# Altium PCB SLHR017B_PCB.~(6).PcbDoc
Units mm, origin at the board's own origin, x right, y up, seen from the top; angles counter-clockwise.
Board outline 79.38 x 53.34 mm, 2 copper layers (Top Layer, Bottom Layer), stack 1.554 mm thick; 59 components, 16 nets, 85 pads, 115 vias.
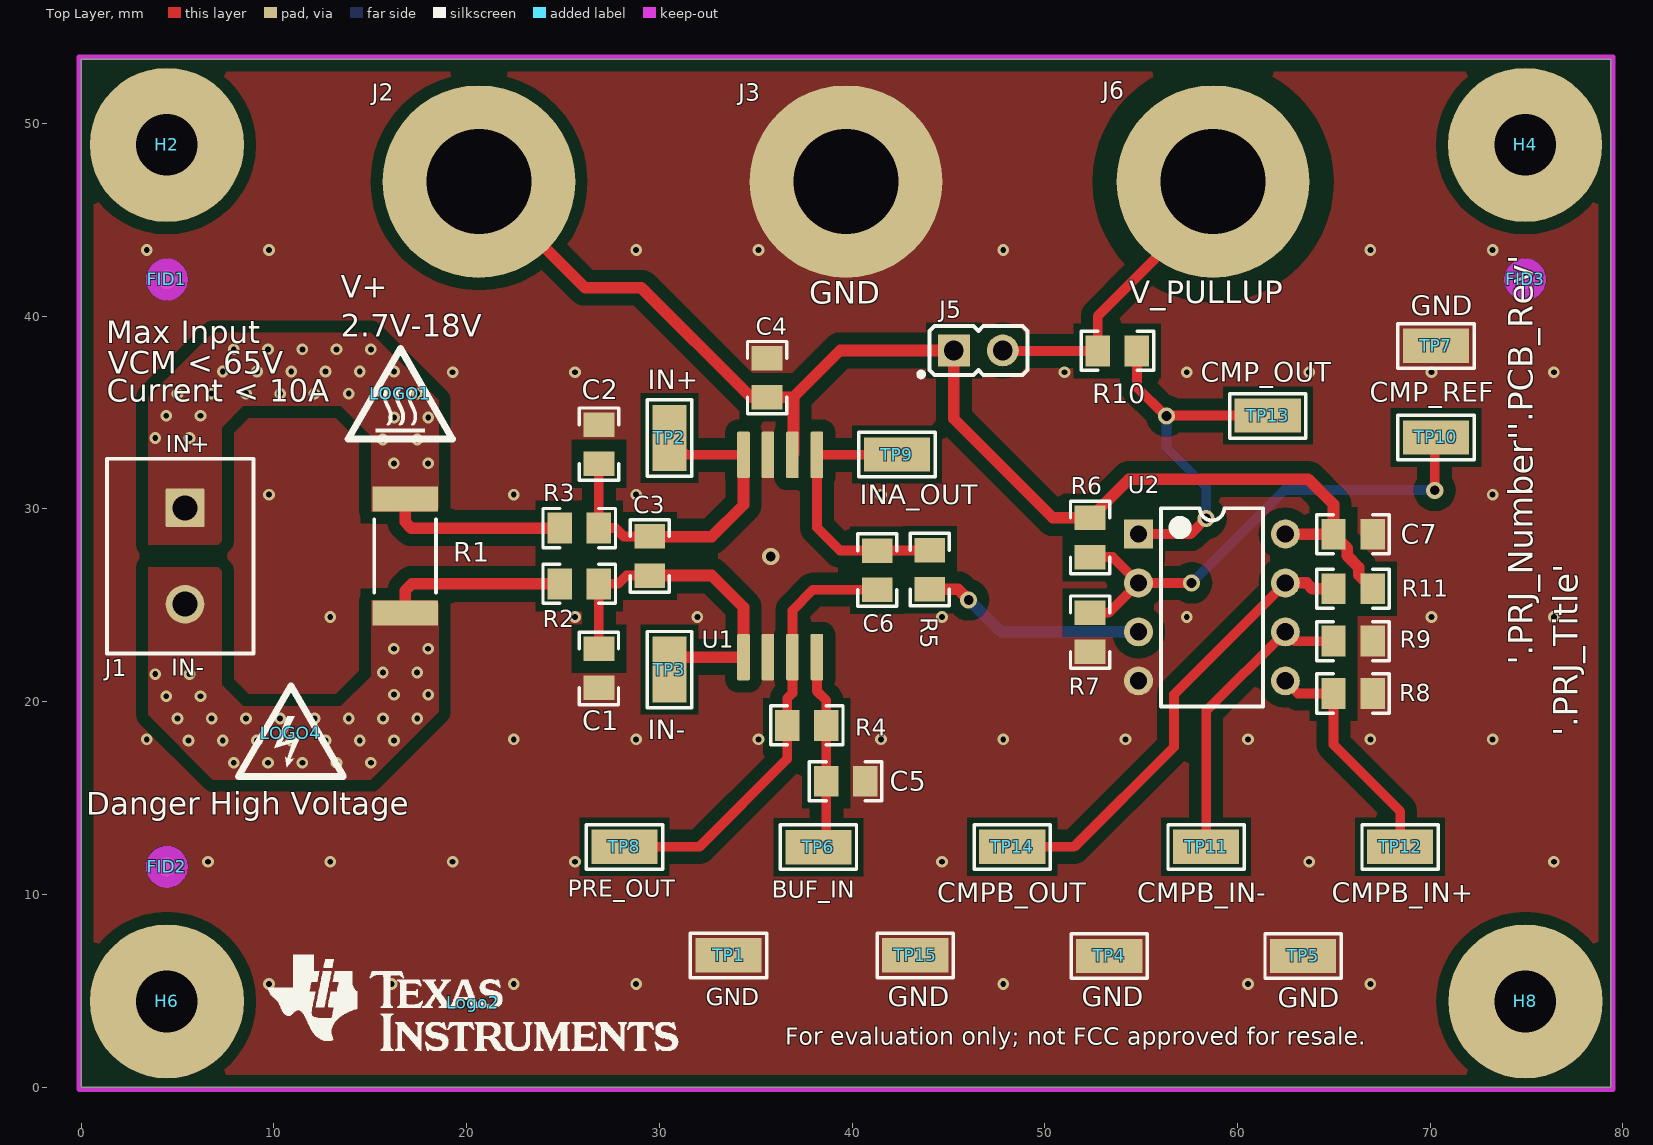
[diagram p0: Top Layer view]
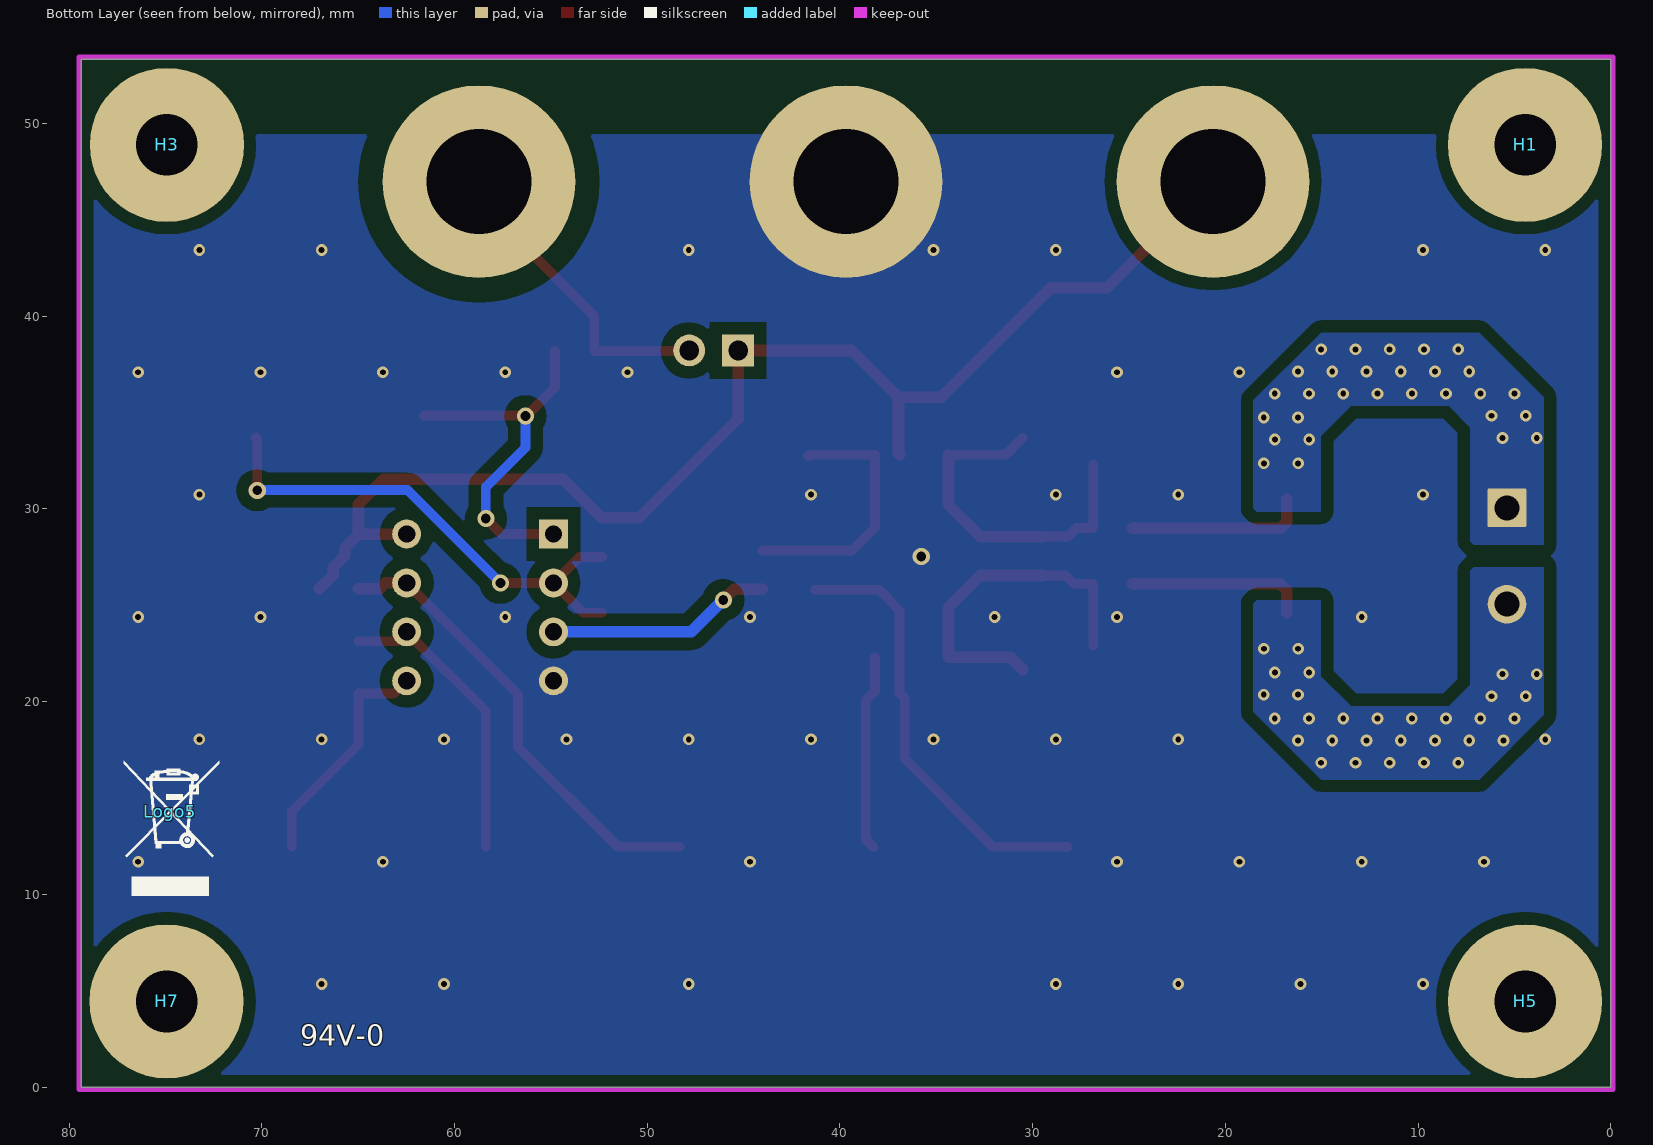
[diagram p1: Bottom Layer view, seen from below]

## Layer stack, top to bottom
Top Solder: solder mask 0.0102, Solder Resist, Dk 3.5
Top Layer: signal copper 0.0533
Dielectric1: core 1.4478, FR-4 High Tg, Dk 4.8
Bottom Layer: signal copper 0.0533
Bottom Solder: solder mask 0.0102, Solder Resist, Dk 3.5

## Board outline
0,0 79.375,0 79.375,53.34 0,53.34
cut-out: -41.052,-51.805 -40.798,-51.805 -40.798,-51.551 -41.052,-51.551

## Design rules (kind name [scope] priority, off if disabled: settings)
AcuteAngle [All] p1: minimum=4.50000000000000E+0001 checktracksonly=FALSE
AssemblyTestPointUsage [All] p1: valid=2
Clearance Clearance_HV [InNetClass('HV_Net')] p1: gap=0.635 ignorepadtopadclearanceinfootprint=TRUE except(1.27: THPad-Poly Poly-Poly)
Clearance Clearance_Keepouts [((IsTrack Or IsArc) And Not InPoly) And IsFree and IsKeepOut vs ((IsTrack Or IsArc) And Not InPoly) And IsFree and IsKeepOut] p2: gap=0 ignorepadtopadclearanceinfootprint=FALSE
Clearance Clearance_Fiducial [InComponentClass('FiducialMark')] p3: gap=0 ignorepadtopadclearanceinfootprint=FALSE
Clearance Clearance_BoardEdge_MountingHoles [OnCopper and InComponentClass('Mounting Holes') vs IsKeepOut] p4: gap=1.016 ignorepadtopadclearanceinfootprint=FALSE except(0.381: Track-THPad)
Clearance Clearance_BoardEdge_Poly [OnCopper and InPoly vs IsKeepOut] p5: gap=0.635 ignorepadtopadclearanceinfootprint=FALSE
Clearance Clearance_Jack_Poly [InPolygon vs InPadClass('Jack')] p6: gap=0.635 ignorepadtopadclearanceinfootprint=FALSE except(1.27: Arc-Poly Track-Poly SMDPad-Poly THPad-Poly Via-Poly Fill-Poly Poly-Poly)
Clearance Clearance_Poly [InPolygon] p7: gap=0.635 ignorepadtopadclearanceinfootprint=FALSE
Clearance [All] p8: gap=0.381 ignorepadtopadclearanceinfootprint=FALSE
ComponentClearance ComponentClearance_MountingHoles_FiducialMarks [InComponentClass('Mounting Holes') vs InComponentClass('FiducialMark')] p1: gap=1.27 collisioncheckmode=3 verticalgap=0.254 showdistances=FALSE
ComponentClearance ComponentClearance_Logo [InComponentClass('Logo')] p2: gap=1.27 collisioncheckmode=3 verticalgap=2540 showdistances=FALSE
ComponentClearance ComponentClearance_ScrewToNut [(HasFootprint('NY PMS 440 0025 PH')) vs (HasFootprint('Keystone_1902C'))] p3: gap=0 collisioncheckmode=3 verticalgap=0 showdistances=FALSE
ComponentClearance ComponentClearance_MountingHoles [InComponentClass('Mounting Holes')] p4: gap=0.762 collisioncheckmode=3 verticalgap=2540 showdistances=FALSE
ComponentClearance [All] p5: gap=0.508 collisioncheckmode=3 verticalgap=0.254 showdistances=FALSE
DiffPairsRouting [All] p1: maxlimit=2.54 minlimit=0.254 mostfreqgap=0.254 toplayer_minwidth=0.381 toplayer_maxwidth=0.381 toplayer_prefwidth=0.381 bottomlayer_minwidth=0.381 bottomlayer_maxwidth=0.381 bottomlayer_prefwidth=0.381 maxuncoupledlength=25.4
FabricationTestPointUsage TestPointUsage [All] p1: valid=2 allowmultiple=FALSE
FabricationTestpoint Testpoint [All] p1: side=3 testpointundercomponent=TRUE minsize=1.016 maxsize=2.54 preferedsize=1.524 minholesize=0 maxholesize=1.016 preferedholesize=0.813 testpointgrid=0.025 allowsidetop=TRUE allowsidebottom=TRUE usegrid=TRUE gridtolerance=0
FanoutControl Fanout_LCC [IsLCC] p1: bgadir=Out bgaviamode=Centered fanoutstyle=Auto fanoutdirection=Alternating viagrid=0.025 // Fanout_LCC (Default Rule)
FanoutControl Fanout_BGA [IsBGA] p2: bgadir=Out bgaviamode=Centered fanoutstyle=Auto fanoutdirection=Alternating viagrid=0.025 // Fanout_BGA (Default Rule)
FanoutControl Fanout_Default [All] p4: bgadir=Out bgaviamode=Centered fanoutstyle=Auto fanoutdirection=Alternating viagrid=0.025 // Fanout_Default (Default Rule)
FanoutControl Fanout_Small [(CompPinCount < 5)] p5: bgadir=Out bgaviamode=Centered fanoutstyle=Auto fanoutdirection=OutThenIn viagrid=0.025 // Fanout_Small (Default Rule)
HoleSize [All] p1: absolutevalues=TRUE maxlimit=6.375 minlimit=0.203 maxpercent=80.000 minpercent=20.000
MinimumAnnularRing [All] p1: minimumring=0.152
MinimumSolderMaskSliver MinimumSolderMaskSliver_Logo [InComponentClass('Logo') vs InComponentClass('Logo')] p1: minsoldermaskwidth=0.018
MinimumSolderMaskSliver [All] p2: minsoldermaskwidth=0.102
PlaneConnect [All] p1: planeconnectstyle=Relief reliefexpansion=0.254 reliefentries=4 reliefconductorwidth=0.254 reliefairgap=0.254
PolygonConnect [All] p1: connectstyle=Direct reliefconductorwidth=0.762 reliefentries=4 polygonreliefangle="90 Angle" airgapwidth=0.381
RoutingVias [All] p1: holewidth=0.305 width=0.61 viastyle="Through Hole" minholewidth=0.127 minwidth=0.127 maxholewidth=0.508 maxwidth=1.016
SilkToBoardRegionClearance [Not ((IsComment or IsDesignator) And (Hide <> 'False')) and not InRegion(1000,500,4000,800)] p1:
SilkToSilkClearance SilkToSilkClearance_Pb-FreeLogo [(HasFootprint('Pb-Free_Overlay_Medium') OR HasFootprint('Pb-Free_Overlay_Small')) vs (HasFootprint('Pb-Free_Overlay_Medium') OR HasFootprint('Pb-Free_Overlay_Small'))] p1: silktosilkclearance=0
SilkToSilkClearance [All] p2: silktosilkclearance=0.102
SilkToSolderMaskClearance SilkToComonentPadClearance [IsPad and InAnycomponent] p1: minsilkscreentomaskgap=0.127 clearancetoexposedcopper=TRUE
SilkToSolderMaskClearance "Silk to Solder Mask Opening" [All] p2: minsilkscreentomaskgap=0.102 clearancetoexposedcopper=FALSE
SolderMaskExpansion [All] p1: expansion=0
Width [All] p1: maxlimit=2.54 minlimit=0.152 preferedwidth=0.254 checkconnectedcopper=TRUE
15 further rules are at their usual default settings.

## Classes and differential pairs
component class Header: J5
component class SLHR017B_MainSheet: C1 C2 C3 C4 C5 C6 C7 C? J1 J2 J3 J5 J6 R1 R2 R3 R4 R5 R6 R7 R8 R9 R10 R11 R14 TP1 TP2 TP3 TP4 TP5 TP6 TP7 TP8 TP9 TP10 TP11 TP12 TP13 TP14 TP15 TP? U1 U2 U4
component class AssemblyNote: ZZ1 ZZ2 ZZ3
component class FiducialMark: FID1 FID2 FID3
component class SLHR017B_Hardware: FID1 FID2 FID3 H1 H2 H3 H4 H5 H6 H7 H8 LOGO1 Logo2 Logo3 LOGO4 Logo5 Logo7 ZZ1 ZZ2 ZZ3
component class Logo: Logo2
component class "Mounting Holes": H2 H4 H6 H8
pad class Jack: J4-1 J6-1 J7-1 J8-1

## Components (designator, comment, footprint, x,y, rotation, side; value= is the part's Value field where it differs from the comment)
C1 "C0805C101J1RACTU" 0805_HV 26.864,21.73 r270 top value=100pF
C2 "C0805C101J1RACTU" 0805_HV 26.87,33.363 r270 top value=100pF
C3 "C0805C101J1RACTU" 0805_HV 29.507,27.559 r270 top value=100pF
C4 "C0805C104K1RACTU" 0805_HV 35.593,36.813 r90 top value=0.1uF
C5 "VJ0805A150JXACW1BC" 0805_HV 39.671,15.87 r0 top value=15pF
C6 "C0805C103F1GACTU" 0805_HV 41.312,26.827 r90 top value=0.01uF
C7 "C0805C104K1RACTU" 0805_HV 66.004,28.687 r0 top value=0.1uF
FID1 "Fiducial" Fiducial10-20 4.445,41.91 r270 top locked
FID2 "Fiducial" Fiducial10-20 4.445,11.43 r0 top locked
FID3 "Fiducial" Fiducial10-20 74.93,41.91 r180 top locked
H1 "1902C" Keystone_1902C 4.445,48.895 r180 bottom locked
H2 "NY PMS 440 0025 PH" "NY PMS 440 0025 PH" 4.445,48.895 r0 top locked
H3 "1902C" Keystone_1902C 74.93,48.895 r180 bottom locked
H4 "NY PMS 440 0025 PH" "NY PMS 440 0025 PH" 74.93,48.895 r0 top locked
H5 "1902C" Keystone_1902C 4.445,4.445 r180 bottom locked
H6 "NY PMS 440 0025 PH" "NY PMS 440 0025 PH" 4.445,4.445 r0 top locked
H7 "1902C" Keystone_1902C 74.943,4.445 r180 bottom locked
H8 "NY PMS 440 0025 PH" "NY PMS 440 0025 PH" 74.943,4.445 r0 top locked
J1 "691137710002" FP-691137710002_HDR2-MFG 5.135,27.559 r270 top
J2 "V+" Keystone_575-4 20.637,46.99 r0 top
J3 "GND" Keystone_575-4 39.687,46.99 r0 top
J5 "PBC02SAAN" Sullins_PBC02SAAN 46.559,38.227 r90 top
J6 "VPULLUP" Keystone_575-4 58.737,46.99 r0 top
LOGO1 "CAUTION HOT SURFACE" IEC_HotSurface_Small 16.56,35.987 r0 top
Logo2 "Texas Instruments" TI_Stacked_Overlay_Small 20.342,4.372 r0 top
Logo3 "FCC disclaimer" FCC_disclaimer 53.912,-33.075 r270 top locked
LOGO4 "DANGER HIGH VOLTAGE" IEC_HighVoltage_Small 10.881,18.359 r0 top
Logo5 "WEEE logo" WEEE_Minimum 74.746,14.294 r180 bottom
R1 "CRA2512-FZ-R025ELF" 2512 16.806,27.559 r90 top value=0.025
R2 "ERJ-6GEY0R00V" 0805_HV 25.844,26.115 r0 top value=0
R3 "ERJ-6GEY0R00V" 0805_HV 25.844,29.009 r0 top value=0
R4 "ERJ-6GEY0R00V" 0805_HV 37.651,18.772 r180 top value=0
R5 "ERJ-6GEY0R00V" 0805_HV 44.03,26.851 r270 top value=0
R6 "ERJ-6GEYJ153V" 0805_HV 52.355,28.519 r90 top value=15k
R7 "ERJ-6GEYJ153V" 0805_HV 52.355,23.605 r90 top value=15k
R8 "RNCP0805FTD10K0" 0805_HV 66.004,20.424 r180 top value=10.0k
R9 "CRCW080510M0FKEA" 0805_HV 66.004,23.142 r180 top value=10.0Meg
R10 "ERJ-6GEYJ153V" 0805_HV 53.772,38.206 r180 top value=15k
R11 "ERJ-6GEYJ153V" 0805_HV 66.004,25.86 r0 top value=15k
TP1 "GND" Testpoint_Keystone_Miniature 33.592,6.844 r0 top
TP2 "IN+" Testpoint_Keystone_Miniature 30.522,33.687 r90 top
TP3 "IN-" Testpoint_Keystone_Miniature 30.522,21.661 r90 top
TP4 "GND" Testpoint_Keystone_Miniature 53.348,6.807 r0 top
TP5 "GND" Testpoint_Keystone_Miniature 63.414,6.807 r0 top
TP6 "BUF_IN" Testpoint_Keystone_Miniature 38.251,12.446 r180 top
TP7 "GND" Testpoint_Keystone_Miniature 70.306,38.47 r0 top
TP8 "PRE_OUT" Testpoint_Keystone_Miniature 28.186,12.472 r0 top
TP9 "INA_OUT" Testpoint_Keystone_Miniature 42.329,32.822 r180 top
TP10 "CMP_REF" Testpoint_Keystone_Miniature 70.3,33.714 r0 top
TP11 "CMPB_IN-" Testpoint_Keystone_Miniature 58.381,12.472 r0 top
TP12 "CMPB_IN+" Testpoint_Keystone_Miniature 68.447,12.472 r0 top
TP13 "CMP_OUT" Testpoint_Keystone_Miniature 61.576,34.848 r0 top
TP14 "CMPB_OUT" Testpoint_Keystone_Miniature 48.315,12.472 r0 top
TP15 "GND" Testpoint_Keystone_Miniature 43.283,6.844 r0 top
U1 "INA901HKX/EM" HKX0008A_Custom_B 36.273,27.561 r90 top
U2 "LM193AJRLQMLV" NAB0008A 58.679,24.892 r0 top
ZZ1 "These assemblies are ESD sensitive, ESD precautions shall be observed." AssemblyNote 116.916,36.926 r0 top
ZZ2 "These assemblies must be clean and free from flux and all contaminants. Use of no clean flux is not acceptable." AssemblyNote 116.916,34.677 r0 top
ZZ3 "These assemblies must comply with workmanship standards IPC-A-610 Class 2, unless otherwise specified." AssemblyNote 116.916,32.428 r0 top

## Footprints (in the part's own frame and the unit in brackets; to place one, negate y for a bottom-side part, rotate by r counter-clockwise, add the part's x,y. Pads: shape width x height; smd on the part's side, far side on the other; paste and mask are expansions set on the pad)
0805_HV [mil] "0805 with 30mil clearance between pads"
  rect 50x63 smd: 1(-40,0) 2(40,0)
  silkscreen extent -74,-40 74,40, body extent -43,-29 43,29, height 57
2512 [mm] "Chip Resistor, Body 6.3x3.2mm, IPC Medium Density"
  rect 1.3x3.4 smd: 1(-2.95,0) 2(2.95,0)
  silkscreen extent -1.9,-1.6 1.9,1.6, body extent -3.22,-1.67 3.22,1.67, height 0.71
AssemblyNote [mm] "Assembly Note"
FCC_disclaimer [mm]
Fiducial10-20 [mm]
  round 1 smd mask+0.5: 1(0,0)
  Top Layer keep-out circle w1.178: c0,0 r0.5
FP-691137710002_HDR2-MFG [mm]
  rrect5% 2x2 hole 1.3 paste-1000 mask+0: 1(-2.5,0.25)
  round 2 hole 1.3 paste-1000 mask+0: 2(2.5,0.25)
  silkscreen extent -5.05,-3.8 5.05,3.8, body extent -5.15,-3.9 5.15,3.9, height 0.25
HKX0008A_Custom_B [mm] "CFP, 8-Leads, Body 6.73x6.74mm (max), Pitch 1.27mm, IPC Medium Density"
  rrect15% 2.4x0.65 smd: 1(-5.25,1.905) 2(-5.25,0.635) 3(-5.25,-0.635) 4(-5.25,-1.905) 5(5.25,-1.905) 6(5.25,-0.635) 7(5.25,0.635) 8(5.25,1.905)
  body extent -3.25,-3.24 3.25,3.24, height 2.51
IEC_HighVoltage_Small [mm]
  silkscreen extent -2.72,-2.24 2.72,2.47
IEC_HotSurface_Small [mm]
  silkscreen extent -2.72,-2.36 2.72,2.35
Keystone_575-4 [mm] "Banana Jack"
  round 10 hole 5.45: 1(0,0)
  body extent -3.95,-3.95 3.92,3.93, height 2.36
Keystone_1902C [mil] "Hex Standoff, 4-40 threaded, nylon"
  round 1 on Mech4: 0(0,0)
  body extent -145,-126 146,126, height 501
NAB0008A [mm] "DIP, 8-Leads, Row Spacing 7.62mm, Pitch 2.54mm, Body 9.78x6.73mm"
  rect 1.5x1.5 hole 0.9: 1(-3.81,3.81)
  round 1.5 hole 0.9: 2(-3.81,1.27) 3(-3.81,-1.27) 4(-3.81,-3.81) 5(3.81,-3.81) 6(3.81,-1.27) 7(3.81,1.27) 8(3.81,3.81)
  silkscreen extent -2.65,-5.15 2.65,5.15, body extent -3.91,-5.08 3.96,5.08, height 5.17
"NY PMS 440 0025 PH" [mm] "4-40 nylon screw and mounting hole"
  round 8 hole 3.2: 1(0,0)
  body extent -3.3,-3.3 3.3,3.3, height 2.69
Sullins_PBC02SAAN [mm] "Sullins 100mil, 1x2, 230 mil above insulator"
  rect 1.65x1.65 hole 1.016: 1(0,1.27)
  round 1.65 hole 1.016: 2(0,-1.27)
  silkscreen extent -1.37,-2.54 1.27,3.1, body extent -1.27,-2.54 1.27,2.54, height 8.38
Testpoint_Keystone_Miniature [mil] "Miniature SMT test point"
  rect 135x70 smd: 1(0,0)
  silkscreen extent -78,-46 78,45, body extent -52,-20 52,20, height 61
TI_Stacked_Overlay_Small [mm]
  silkscreen extent -10.63,-2.49 10.63,2.49
WEEE_Minimum [mm] "WEEElie bin"
  silkscreen extent -2.42,-4.38 2.52,2.65

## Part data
C1 C2 C3: library part CMP-0007706-2, "CAP, CERM, 100 pF, 100 V, +/- 5%, X7R, 0805", Cap_Case=0805, Manufacturer=Kemet, Supplier Part Number 1=80-C0805C101J1R, TempCo=X7R, Tolerance_%=5%, Value1=Unknown, Value2=100V, ValueDisplayed=100pF
C4 C7: library part CMP-0007722-2, "CAP, CERM, 0.1 uF, 100 V, +/- 10%, X7R, 0805", Cap_Case=0805, Manufacturer=Kemet, Supplier Part Number 1=399-3486-1-ND, TempCo=X7R, Tolerance_%=10%, Value1="0.064 ohm", Value2=100V, ValueDisplayed=0.1uF
C5: library part CMP-0008431-2, "CAP, CERM, 15 pF, 50 V, +/- 5%, C0G/NP0, 0805", Cap_Case=0805, Manufacturer=Vishay-Bccomponents, Supplier Part Number 1=BC1258CT-ND, TempCo=C0G/NP0, Tolerance_%=5%, Value1=Unknown, Value2=50V, ValueDisplayed=15pF
C6: library part CMP-0007716-2, "CAP, CERM, 0.01 uF, 100 V, +/- 1%, C0G/NP0, 0805", Cap_Case=0805, Manufacturer=Kemet, Supplier Part Number 1=399-11160-1-ND, TempCo=C0G/NP0, Tolerance_%=1%, Value1=Unknown, Value2=100V, ValueDisplayed=0.01uF
FID1 FID2 FID3: library part CMP-0077181-1, "Fiducial mark.  There is nothing to buy or mount.", Manufacturer=N/A
H1 H3 H5 H7: library part CMP-0003610-1, "Standoff, Hex, 0.5\"L #4-40 Nylon", Manufacturer=Keystone, Supplier Part Number 1=36-1902C-ND
H2 H4 H6 H8: library part CMP-0003617-1, "Machine Screw, Round, #4-40 x 1/4, Nylon, Philips panhead", Manufacturer="B&F Fastener Supply", Supplier Part Number 1=H542-ND
J1: library part CMP-0087503-1, "TERM BLK 2POS SIDE ENTRY 5MM PCB", Current_A=16A, Manufacturer="Würth Elektronik", Voltage_V=300V
J2 J3 J6: library part CMP-0055165-2, "Standard Banana Jack, Uninsulated, 5.5mm", Manufacturer=Keystone, PartNumber=575-4, Supplier Part Number 1=36-575-4-ND
J5: library part CMP-0054566-1, "Header, 100mil, 2x1, Gold, TH", Color=Black, Current_A=3A, Manufacturer="Sullins Connector Solutions", Supplier Part Number 1=S1011E-02-ND, Voltage_V=1.8kV
LOGO1: library part CMP-0074837-1, "IEC 61010-1 Hot Surface Warning"
Logo2: library part CMP-0074838-1, "Texas Instrument Corporate Signature"
Logo3: library part CMP-0074847-1, "FCC_disclaimer"
LOGO4: library part CMP-0074835-1, "IEC 61010-1 High Voltage Warning"
Logo5: library part CMP-0074769-1
R1: library part CMP-0015421-2, "RES, 0.025, 1%, 3 W, 2512", Manufacturer=Bourns, Power_W=3W, Supplier Part Number 1=652-CRA2512FZR025ELF, TempCo="75 ppm/C", Tolerance_%=1%, Value_Code=R025, ValueDisplayed=0.025
R2 R3 R4 R5: library part CMP-0020616-3, "RES, 0, 5%, 0.125 W, AEC-Q200 Grade 0, 0805", Manufacturer=Panasonic, Power_W=125mW, Supplier Part Number 1=P0.0ACT-ND, TempCo="600 ppm/C", Tolerance_%=5%, Value2=0.125W, Value_Code=0000, ValueDisplayed=0
R6 R7 R10 R11: library part CMP-0020646-3, "RES, 15 k, 5%, 0.125 W, AEC-Q200 Grade 0, 0805", Manufacturer=Panasonic, Power_W=125mW, Supplier Part Number 1=P15KACT-ND, TempCo="200 ppm/C", Tolerance_%=5%, Value2=0.125W, Value_Code=15k0, ValueDisplayed=15k
R8: library part CMP-0084247-1, "RES, 10.0 k, 1%, 0.25 W, AEC-Q200 Grade 0, 0805", Manufacturer="Stackpole Electronics Inc", Power_W=250mW, TempCo="100 ppm/C", Tolerance_%=1%, Value2=0.25W, Value_Code=10k0, ValueDisplayed=10.0k
R9: library part CMP-0020846-3, "RES, 10.0 M, 1%, 0.125 W, AEC-Q200 Grade 0, 0805", Manufacturer=Vishay-Dale, Power_W=125mW, Supplier Part Number 1=541-10.0MCCT-ND, TempCo="100 ppm/C", Tolerance_%=1%, Value2=0.125W, Value_Code=10M0, ValueDisplayed=10.0M
TP1 TP2 TP3 TP4 TP5 TP6 TP7 TP8 TP9 TP10 TP11 TP12 TP13 TP14 TP15: library part CMP-0055152-1, "Test Point, Miniature, SMT", Manufacturer=Keystone, PartNumber=5015, Supplier Part Number 1=36-5015TR-ND
U1: library part CMP-0081563-2, "Voltage Output, Unidirectional Measurement Current-Shunt Monitor, HKX0008A (CFP-8)", Alternate Manufacturer="Texas Instruments", Rating=Space
U2: library part CMP-0067897-1, "Low Power Low Offset Voltage Dual Comparator, 8-pin CerDIP", Manufacturer="Texas Instruments", Package Reference=NAB0008A, PackageTopMarking="NSZSSXXYYA*LM193AJRLV Q*5962R*9452603VPA", PowerWise=N
ZZ1: library part CMP-0077236-1
ZZ2: library part CMP-0077237-1
ZZ3: library part CMP-0077238-1

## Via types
v1: diameter 0.61, hole 0.305, Top Layer to Bottom Layer, tented both sides, 109 vias
v2: diameter 0.889, hole 0.508, Top Layer to Bottom Layer, tented both sides, 6 vias

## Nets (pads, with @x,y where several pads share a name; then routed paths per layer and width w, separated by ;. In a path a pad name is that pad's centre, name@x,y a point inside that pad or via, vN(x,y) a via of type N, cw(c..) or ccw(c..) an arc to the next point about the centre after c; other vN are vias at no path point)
GND: C1.2 C2.1 C4.2 C5.2 C7.2 J3.1 R7.1 R8.1 R9.1 TP1.1 TP4.1 TP5.1 TP7.1 TP15.1 U1.2 U1.7 U2.4
  other v1: 9.748,5.345 16.098,5.345 22.448,5.345 28.798,5.345 47.848,5.345 60.548,5.345 66.898,5.345 6.573,11.695 12.923,11.695 19.273,11.695 25.623,11.695 44.673,11.695 63.723,11.695 76.423,11.695 3.398,18.045 22.448,18.045 28.798,18.045 35.148,18.045 41.498,18.045 47.848,18.045 54.198,18.045 60.548,18.045 66.898,18.045 73.248,18.045 12.923,24.395 25.623,24.395 31.973,24.395 44.673,24.395 57.373,24.395 70.073,24.395 76.423,24.395 9.748,30.745 22.448,30.745 28.798,30.745 41.498,30.745 73.248,30.745 19.273,37.095 25.623,37.095 51.023,37.095 57.373,37.095 63.723,37.095 70.073,37.095 76.423,37.095 3.398,43.445 9.748,43.445 28.798,43.445 35.148,43.445 47.848,43.445 66.898,43.445 73.248,43.445
  other v2: 35.784,27.539
NetC1_1: C1.1 C3.2 R2.2 TP3.1 U1.1 | length 18.3
  Top Layer w0.508: C1.1@26.86,22.898 R2.2 27.862,26.115 28.294,26.547 C3.2@29.507,26.547
  Top Layer w0.6: C3.2@29.507,26.547 32.728,26.547 34.368,24.907 U1.1 31.172,22.311 TP3.1
NetC2_2: C2.2 C3.1 R3.2 TP2.1 U1.8 | length 18.5
  Top Layer w0.508: C2.2@26.86,32.315 R3.2 27.719,29.009 28.153,28.575 C3.1 ; TP2.1 31.397,32.811 U1.8
  Top Layer w0.6: C3.1@29.507,28.571 32.728,28.571 34.368,30.211 U1.8@34.368,32.807
NetC5_1: C5.1 R4.1 TP6.1 U1.4 | length 10.2
  Top Layer w0.508: U1.4 38.178,20.543 38.667,20.054 R4.1 38.667,12.863 TP6.1
NetC6_1: C6.1 R4.2 TP8.1 U1.3 | length 23
  Top Layer w0.508: TP8.1 32.086,12.472 36.635,17.02 R4.2 36.635,20.17 36.908,20.443 U1.3 36.908,24.738 37.981,25.811 C6.1
NetC6_2: C6.2 R5.1 TP9.1 U1.5 | length 13.6
  Top Layer w0.508: TP9.1@41.653,32.754 41.596,32.811 U1.5 38.178,29.046 39.381,27.843 C6.2 R5.1@44.021,27.843
NetJ1_1: J1.1 R1.2 R3.1 | length 9.3
  Top Layer w0.6: R1.2 16.806,29.33 17.127,29.009 R3.1
  other v1: 16.224,32.369 18.002,32.369 15.653,33.603 17.431,33.603 3.839,33.688 5.617,33.688 16.228,34.752 18.006,34.752 4.414,34.837 6.192,34.837 4.989,35.986 6.767,35.986 8.545,35.986 10.323,35.986 12.101,35.986 13.879,35.986 15.657,35.986 17.435,35.986 7.342,37.135 9.12,37.135 10.898,37.135 12.676,37.135 14.454,37.135 16.232,37.135 7.917,38.284 9.695,38.284 11.473,38.284 13.251,38.284 15.029,38.284
NetJ1_2: J1.2 R1.1 R2.1 | length 9.3
  Top Layer w0.6: R1.1 16.806,25.756 17.165,26.115 R2.1
  other v1: 7.917,16.834 9.695,16.834 11.473,16.834 13.251,16.834 15.029,16.834 5.564,17.983 7.342,17.983 9.12,17.983 10.898,17.983 12.676,17.983 14.454,17.983 16.232,17.983 4.989,19.132 6.767,19.132 8.545,19.132 10.323,19.132 12.101,19.132 13.879,19.132 15.657,19.132 17.435,19.132 4.414,20.281 6.192,20.281 16.228,20.366 18.006,20.366 3.839,21.43 5.617,21.43 15.653,21.515 17.431,21.515 16.224,22.749 18.002,22.749
NetJ5_2: J5.2 J6.1 R10.2 | length 16.2
  Top Layer w0.508: J5.2 47.85,38.206 R10.2 52.756,40.028 58.737,46.009 J6.1
NetR5_2: R5.2 U2.3 | length 11.8
  Top Layer w0.6: R5.2 45.501,25.835 v2(46.053,25.283)
  Bottom Layer w0.6: v2(46.053,25.283) 47.714,23.622 U2.3
NetR6_1: R6.1 R7.2 TP10.1 U2.2 | length 26.4
  Top Layer w0.508: R7.2 53.328,24.621 U2.2 ; R6.1 53.528,27.503 U2.2 ; v2@57.57,26.178 57.554,26.162 U2.2 ; v2(70.238,30.969) 70.238,33.651 TP10.1
  Bottom Layer w0.508: v2(57.623,26.163) 62.449,30.988 v2@70.276,30.988
NetR8_2: R8.2 TP12.1 U2.5 | length 12.2
  Top Layer w0.508: U2.5 63.147,20.424 R8.2 64.988,17.776 68.447,14.317 TP12.1
NetR9_2: R9.2 TP11.1 U2.6 | length 15.5
  Top Layer w0.508: TP11.1 58.381,19.514 U2.6 62.969,23.142 R9.2
NetR10_1: R10.1 TP13.1 U2.1 | length 19.3
  Top Layer w0.508: R10.1 54.788,36.316 56.256,34.848 TP13.1 ; U2.1 57.578,28.702 v2(58.378,29.501)
  Bottom Layer w0.508: v2(56.322,34.826) 56.322,33.195 58.378,31.139 v2(58.378,29.501)
NetR11_1: R11.1 TP14.1 U2.7 | length 24.1
  Top Layer w0.508: TP14.1 51.532,12.472 56.703,17.642 56.703,20.376 U2.7
  Top Layer w0.6: U2.7 63.588,26.162 63.89,25.86 R11.1
V+: C4.1 C7.1 J2.1 J5.1 R6.2 R11.2 U1.6 U2.8 | length 67.8
  Top Layer w0.6: J2.1 26.146,41.482 29.064,41.482 34.738,35.808 36.961,35.808 ; U1.6 36.961,32.865 36.961,35.808 ; U2.8 62.503,28.687 C7.1 ; R11.2 66.304,26.576 66.304,26.966 65.704,27.566 65.704,27.971 C7.1 ; 36.961,35.808 39.38,38.227 J5.1 45.289,34.673 50.427,29.535 R6.2 54.372,31.552 63.676,31.552 64.988,30.24 C7.1
pads on no net: FID1.1 FID2.1 FID3.1 H1.0 H2.1 H3.0 H4.1 H5.0 H6.1 H7.0 H8.1

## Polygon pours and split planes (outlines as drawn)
NetJ1_2 on Bottom Layer "NETJ1_2_L02_P290" (solid, remove dead copper, pour order 290): 3.478,26.977 7.285,26.981 7.285,20.89 8.413,19.762 13.469,19.759 15.045,21.333 15.046,25.255 18.541,25.264 18.541,19.469 15.033,15.961 6.832,15.961 3.478,19.315
NetJ1_1 on Bottom Layer "NETJ1_1_L02_P292" (solid, remove dead copper, pour order 292): 3.478,28.141 7.285,28.137 7.285,34.228 8.413,35.356 13.469,35.359 15.045,33.785 15.046,29.863 18.541,29.854 18.541,35.649 15.033,39.157 6.832,39.157 3.478,35.803
GND on Bottom Layer "GND" (solid, remove dead copper, pour order 298): -0.316,-3.881 79.055,-3.881 79.055,49.459 79.055,49.46 -0.315,49.46 -0.318,49.457
GND on Top Layer "GND_L01_P300" (solid, remove dead copper, pour order 300): -0.111,53.502 -0.109,53.5 79.261,53.5 79.261,0.16 -0.114,0.16
NetJ1_2 on Top Layer "NETJ1_2_L01_P294" (solid, remove dead copper, pour order 294): 3.478,26.977 7.285,26.981 7.285,20.89 8.413,19.762 13.469,19.759 15.045,21.333 15.046,25.255 18.541,25.264 18.541,19.469 15.033,15.961 6.832,15.961 3.478,19.315
NetJ1_1 on Top Layer "NETJ1_1_L01_P288" (solid, remove dead copper, pour order 288): 3.478,28.141 7.285,28.137 7.285,34.228 8.413,35.356 13.469,35.359 15.045,33.785 15.046,29.863 18.541,29.854 18.541,35.649 15.033,39.157 6.832,39.157 3.478,35.803

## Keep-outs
Keep-Out Layer:
  lines w0.254: -0.127,-0.127 79.502,-0.127 79.502,53.467 -0.127,53.467 -0.127,-0.127
  text ".Layer_Name" at -8.82,-34.647 h1.52

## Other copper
Top Layer:
  text ".Layer_Name" at -8.82,-34.647 h1.52
Bottom Layer:
  text ".Layer_Name" at -8.82,-34.647 h1.52

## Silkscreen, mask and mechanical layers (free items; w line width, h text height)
Top Overlay:
  text "V_PULLUP" at 54.395,40.283 h2
  text "GND" at 37.785,40.25 h2
  text "V+ / 2.7V-18V" at 13.467,38.562 h2
  text "Max Input" at 1.303,38.225 h2
  text "VCM < 65V" at 1.363,36.624 h2
  text "Current < 10A" at 1.321,35.171 h2
  text "IN+" at 4.38,32.955 h0.89
  text "'.PRJ_Number''.PCB_Rev'" at 75.327,21.909 h1.27 r90
  text "IN-" at 4.666,21.336 h0.89
  text "'.PRJ_Title'" at 77.67,18.206 h1.27 r90
  text "Danger High Voltage" at 0.266,13.747 h2
  text ".Layer_Name" at -8.82,-34.647 h1.52
Bottom Overlay:
  text "94V-0" at 68.001,1.778 h1.85
  text ".Layer_Name" at -8.82,-34.647 h1.52
Top Paste:
  text ".Layer_Name" at -8.82,-34.647 h1.52
Bottom Paste:
  text ".Layer_Name" at -8.82,-34.647 h1.52
Top Solder:
  text ".Layer_Name" at -8.82,-34.647 h1.52
  text ".Layer_Name" at -8.82,-34.647 h1.52
Bottom Solder:
  text ".Layer_Name" at -8.82,-34.647 h1.52
Drill Guide:
  text ".Layer_Name" at -8.82,-34.647 h1.52
M1 Board Outline:
  the board outline again, w0.254
  text ".Layer_Name" at -8.82,-34.647 h1.52
M2 Board Dimensions:
  rectangle: -20.3,-23.001 -10.775,-19.826
  rectangle: -23.475,-19.826 -20.3,-16.651
  lines w0.178: -23.475,-19.826 1.925,-19.826 ; -20.3,-23.001 -20.3,-16.651 ; -17.125,-23.001 -17.125,-16.651 ; -10.775,-23.001 -10.775,-16.651 ; -4.425,-23.001 -4.425,-16.651 ; -23.475,-23.001 -23.475,-16.651 1.925,-16.651 1.925,-23.001 -23.475,-23.001
  text ".Layer_Name" at -8.82,-34.647 h1.52
M3 3D STEP Top:
  text ".Layer_Name" at -8.82,-34.647 h1.52
M4 3D STEP Bottom:
  text ".Layer_Name" at -8.82,-34.647 h1.52
M5 Assembly Top:
  lines w0.254: -30.892,-36.468 136.748,-36.468 ; -30.892,-31.303 136.799,-31.303 ; -30.892,-26.138 -30.892,-41.632 70.835,-41.632 136.799,-41.632 136.799,-26.138 -30.88,-26.138 -30.88,-41.632 9.138,-41.632 ; 31.719,-41.632 31.719,-26.138 ; 63.901,-31.303 63.901,-26.138 ; 85.237,-31.303 85.237,-26.138 ; 101.035,-41.797 101.035,-36.645
  text "COMPONENTS MARKED 'DNP' SHOULD NOT BE POPULATED." at 5.823,-20.931 h1.52
  text "ASSEMBLY VARIANT:" at 5.811,-23.865 h1.52
  text ".VariantName" at 32.125,-23.865 h1.52
  text "PCB VIEWED FROM TOP SIDE" at -29.279,-29.495 h1.52
  text "BOARD #:" at 33.624,-29.495 h1.52
  text ".PRJ_Number" at 47.479,-29.495 h1.52
  text "REV:" at 68.93,-29.495 h1.52
  text ".PCB_Rev" at 76.334,-29.495 h1.52
  text "SVN REV:" at 90.215,-29.495 h1.52
  text ".VersionControl_RevNumber" at 103.067,-29.495 h1.52
  text "TID #:" at 33.624,-34.66 h1.52
  text ".TID" at 47.479,-34.66 h1.52
  text "PLOT NAME =" at -29.279,-39.875 h1.52
  text ".plot_File_Name" at -8.82,-39.875 h1.52
  text "GENERATED    :" at 33.675,-39.875 h1.52
  text ".Print_Date" at 55.76,-39.875 h1.52
  text ".Print_Time" at 74.276,-39.875 h1.52
  text "TEXAS INSTRUMENTS" at 106.395,-39.875 h1.52
M6 Assembly Bottom:
  lines w0.254: -30.905,-31.316 136.786,-31.316 ; -30.854,-36.48 136.786,-36.48 ; 4.858,-41.81 4.858,-36.658 ; 20.657,-31.316 20.657,-26.151 ; 41.993,-31.316 41.993,-26.151 ; 74.175,-41.645 74.175,-26.151 ; 96.755,-41.645 136.773,-41.645 136.773,-26.151 -30.905,-26.151 -30.905,-41.645 35.059,-41.645 136.786,-41.645 136.786,-26.151
  text "COMPONENTS MARKED 'DNP' SHOULD NOT BE POPULATED." at 131.515,-20.918 h1.52
  text ".VariantName" at 104.998,-23.865 h1.52
  text "ASSEMBLY VARIANT:" at 131.388,-23.865 h1.52
  text ".VersionControl_RevNumber" at 2.826,-29.508 h1.52
  text "SVN REV:" at 15.679,-29.508 h1.52
  text ".PCB_Rev" at 29.56,-29.508 h1.52
  text "REV:" at 36.964,-29.508 h1.52
  text ".PRJ_Number" at 58.414,-29.508 h1.52
  text "BOARD #:" at 72.27,-29.508 h1.52
  text "PCB VIEWED FROM BOTTOM SIDE" at 135.173,-29.508 h1.52
  text ".TID" at 58.414,-34.673 h1.52
  text "TID #:" at 72.27,-34.673 h1.52
  text "TEXAS INSTRUMENTS" at -0.501,-39.888 h1.52
  text ".Print_Time" at 31.617,-39.888 h1.52
  text ".Print_Date" at 50.134,-39.888 h1.52
  text "GENERATED    :" at 72.219,-39.888 h1.52
  text ".plot_File_Name" at 114.713,-39.888 h1.52
  text "PLOT NAME =" at 135.173,-39.888 h1.52
M7 LPKF Text Top:
  text ".Layer_Name" at -8.82,-34.647 h1.52
M8 LPKF Text Bottom:
  text ".Layer_Name" at -8.82,-34.647 h1.52
M9 Title Sheet:
  drawing of 57 lines, arcs and shapes, not listed
  text "1" at -4.684,191.286 h1.78
  text "2" at 58.706,191.286 h1.78
  text "3" at 121.936,191.286 h1.78
  text "4" at 185.605,191.286 h1.78
  text "5" at 249.079,191.286 h1.78
  text "6" at 312.706,191.286 h1.78
  text "A" at -34.055,162.254 h1.78
  text "A" at 341.865,162.254 h1.78
  text "B" at -34.055,101.802 h1.78
  text "B" at 341.865,101.802 h1.78
  text "C" at -34.055,41.477 h1.78
  text "C" at 341.865,41.477 h1.78
  text "PROJECT TITLE:" at 264.649,-5.793 h1.14
  text ".PRJ_Title" at 265.919,-9.179 h1.78
  text "DESIGNED FOR:" at 264.649,-13.438 h1.14
  text ".PRJ_Customer" at 265.919,-16.994 h1.78
  text "D" at -34.055,-18.721 h1.78
  text "D" at 341.865,-18.721 h1.78
  text "FILE NAME:" at 264.649,-21.058 h1.14
  text ".PCB_File_Name_No_Path" at 265.919,-24.106 h1.78
  text "Texas Instruments (TI) and/or its licensors do not warrant the accuracy or completeness of this specification" at 138.424,-28.217 h1.14
  text "ENGINEER:" at 264.649,-28.424 h1.14
  text "LAYOUT BY:" at 302.876,-28.424 h1.14
  text "or any information contained therein. TI and/or its licensors do not warrant that this design will meet" at 137.282,-31.079 h1.14
  text ".PRJ_Engineer" at 265.919,-32.361 h1.78
  text ".PCB_Layout" at 304.159,-32.361 h1.78
  text "the specifications, will be suitable for your application or fit for any particular purpose, or will operate in" at 137.282,-33.94 h1.14
  text ".Layer_Name" at -8.82,-34.647 h1.52
  text "ALTIUM DESIGNER VERSION:" at 302.876,-36.298 h1.14
  text "an implementation. TI and/or its licensors do not warrant that the design is production worthy. You should" at 137.282,-36.802 h1.14
  text "completely validate and test your design implementation to confirm the system functionality for your application." at 138.424,-39.664 h1.14
  text ".print_Scale" at 265.919,-39.685 h1.78
  text ".Application_BuildNumber" at 304.159,-39.685 h1.78
  text "1" at -4.684,-44.934 h1.78
  text "2" at 58.706,-44.934 h1.78
  text "3" at 121.936,-44.934 h1.78
  text "4" at 185.605,-44.934 h1.78
  text "5" at 249.079,-44.934 h1.78
  text "6" at 296.265,-45.082 h1.78
  text "WO#307451-7449-D" at 306.423,-45.145 h1.78
M10 Fab Notes:
  drawing of 189 lines, arcs and shapes, not listed
  text "DESIGN INFORMATION" at 291.371,148.606 h1.52
  text "20" at 301.796,145.27 h1.52
  text "MIN. TRACK WIDTH:" at 274.999,145.25 h1.52
  text "MIL" at 306.774,145.25 h1.52
  text "MIN. CLEARANCE:" at 274.999,142.097 h1.52
  text "MIL" at 306.774,142.097 h1.52
  text "19.7" at 300.638,142.035 h1.52
  text "24" at 301.312,139.159 h1.52
  text "MIN. VIA PAD SIZE:" at 274.999,138.944 h1.52
  text "MIL" at 306.774,138.944 h1.52
  text "0.05mm (2MIL)" at 292.652,135.644 h1.52
  text "MINIMUM ANNULAR RING" at 266.636,135.436 h1.52
  text "EXTERNAL" at 310.635,135.436 h1.52
  text "PER" at 271.716,132.638 h1.52
  text "IPC-D-275 CLASS 2 LEVEL C" at 277.304,132.638 h1.52
  text "MIL, HOLES" at 315.106,130.086 h1.52
  text "+/-" at 305.137,129.868 h1.52
  text "+/-" at 326.829,129.868 h1.52
  text "REGISTRATION TOLERANCES:" at 266.636,129.841 h1.52
  text "METAL" at 297.111,129.841 h1.52
  text "5" at 311.746,129.841 h1.52
  text "3" at 332.904,129.841 h1.52
  text "MIL" at 335.857,129.841 h1.52
  text "HOLE SIZE TOLERANCE (UNLESS OTHERWISE SPECIFIED):" at 266.636,127.344 h1.52
  text "+/-" at 326.829,127.271 h1.52
  text "3" at 332.904,127.244 h1.52
  text "MIL" at 335.857,127.244 h1.52
  text "MATERIAL:" at 264.737,123.748 h1.52
  text "FR-4 High Tg" at 289.793,120.483 h1.52
  text "FR-408" at 275.431,120.166 h1.52
  text "OTHER" at 313.226,120.166 h1.52
  text "X" at 286.026,120.128 h1.52
  text "62 MIL (1.6mm) +/-10%" at 283.561,116.533 h1.52
  text "X" at 280.511,116.47 h1.52
  text "THICKNESS:" at 266.636,116.324 h1.52
  text "OTHER" at 316.198,116.324 h1.52
  text "TOLERANCE:" at 266.636,112.811 h1.52
  text "X" at 288.182,112.811 h1.52
  text "ANSI IPC-6012 TYPE 3 CLASS 2" at 292.703,112.811 h1.52
  text "OTHER +/-" at 292.703,109.148 h1.52
  text "BOW & TWIST:" at 266.636,105.46 h1.52
  text "X" at 288.182,105.46 h1.52
  text "ANSI IPC-6012 TYPE 3 CLASS 2" at 292.703,105.46 h1.52
  text "OTHER +/-" at 292.703,101.734 h1.52
  text "DRILLING:" at 264.737,98.417 h1.52
  text "NC_DRILL FILES" at 309.467,95.745 h1.52
  text "REFERENCE:" at 266.636,95.645 h1.52
  text "X" at 283.33,95.642 h1.52
  text "AS SHOWN" at 287.851,95.645 h1.52
  text "X" at 306.216,95.645 h1.52
  text "OTHER" at 317.036,92.032 h1.52
  text "PTH COPPER THICKNESS:" at 266.628,91.942 h1.52
  text "X" at 295.565,91.942 h1.52
  text "20-30 um" at 298.816,91.942 h1.52
  text "BOARD FINISH:" at 264.737,88.193 h1.52
  text "SILKSCREEN:" at 268.68,85.396 h1.52
  text "X" at 293.008,85.396 h1.52
  text "TOP" at 295.979,85.396 h1.52
  text "BOTTOM" at 308.959,85.396 h1.52
  text "SILKSCREEN COLOR:" at 268.68,81.454 h1.52
  text "X" at 292.982,81.454 h1.52
  text "WHITE" at 295.979,81.454 h1.52
  text "OTHER" at 308.959,81.454 h1.52
  text "X" at 296.222,77.91 h1.52
  text "GREEN" at 299.307,77.81 h1.52
  text "OTHER" at 315.004,77.81 h1.52
  text "SOLDER RESIST COLOR:" at 268.68,77.636 h1.52
  text "X" at 296.31,73.892 h1.52
  text "MATTE" at 299.307,73.892 h1.52
  text "SEMI-GLOSS" at 314.992,73.876 h1.52
  text "IMMERSION GOLD (ENIG)" at 291.687,69.504 h1.52
  text "ENEPIG" at 325.66,69.321 h1.52
  text "SURFACE FINISH:" at 264.737,69.295 h1.52
  text "X" at 287.166,69.295 h1.52
  text "IMM. TIN/SILVER OR EQUIV" at 273.108,65.807 h1.52
  text "OTHER" at 309.467,65.707 h1.52
  text "ARRAY/PANEL:" at 264.737,61.761 h1.52
  text "CUT AND TRIM PER M1 BOARD OUTLINE" at 291.687,61.552 h1.52
  text "N.C. ROUTE" at 291.687,58.098 h1.52
  text "V. SCORE" at 313.683,58.098 h1.52
  text "X" at 309.04,58.058 h1.52
  text "CERTIFICATION:" at 264.737,54.819 h1.52
  text "MATERIALS AND WORKMANSHIP FOR ALL PCBS" at 283.152,54.819 h1.52
  text "TO MEET OR EXCEED THE REQUIREMENTS OF:" at 283.152,52.429 h1.52
  text "X" at 273.945,49.162 h1.52
  text "ANSI IPC-A-600F CLASS ->" at 277.196,49.162 h1.52
  text "X" at 319.055,49.162 h1.52
  text "2" at 321.849,49.162 h1.52
  text "1" at 313.848,49.124 h1.52
  text "3" at 330.841,49.124 h1.52
  text "X" at 294.57,45.411 h1.52
  text "RoHS" at 297.821,45.411 h1.52
  text "OTHER" at 314.189,45.411 h1.52
  text "PER ORDER" at 324.274,45.411 h1.52
  text "ALL BOARDS MUST MEET OR EXCEED UL94-V0 REQUIREMENTS." at 265.437,41.504 h1.52
  text "PCB MUST BEAR THE UL94V-0 UL REGISTERED MATERIAL ID NUMBER" at 265.437,38.556 h1.52
  text "ADDITIONAL REQUIREMENTS:" at 264.737,34.252 h1.52
  text "MICROSECTION:" at 266.636,31.531 h1.52
  text "YES" at 289.642,31.531 h1.52
  text "REQUIRED" at 311.524,27.865 h1.52
  text "BARE BOARD ELEC. TEST:" at 266.636,27.793 h1.52
  text "NONE" at 299.802,27.793 h1.52
  text "X" at 308.527,27.793 h1.52
  text "PER ORDER" at 326.561,27.793 h1.52
  text "XX MIL VIAS REQUIRE NON-CONDUCTIVE FILL AND PLANARIZE" at 270.907,22.587 h1.5
  text "XX MIL VIAS REQUIRE CONDUCTIVE FILL AND PLANARIZE" at 271.111,19.946 h1.52
  text "FAB NOTES:" at 112.995,18.337 h1.52
  text "OUTER XX MIL VIAS REQUIRE 50 OHM SINGLE-ENDED IMPEDANCE" at 271.086,15.796 h1.47
  text "1. THE SOLDER MASK IMAGES THAT ARE THE SAME SIZE AS THE COMPONENT PADS MAY BE ENLARGED AS PER THE" at 113.298,14.574 h1.52
  text "LAYER 2 & 3 (INNER LAYERS) XX MIL WIDE, XX MIL SPACE" at 271.089,11.861 h1.52
  text "MANUFACTURING CAPABILITIES BUT NOT BEYOND 0.08MM PER SIDE OR 0.15MM OVERALL." at 117.396,11.181 h1.52
  text "ALL OTHER SOLDER MASK IMAGES SHALL NOT BE MODIFIED." at 117.396,7.787 h1.52
  text ".Layer_Name" at -8.82,-34.647 h1.52
M11 Gerber Information:
  lines w0.254: -30.892,-36.468 136.748,-36.468 ; -30.892,-31.303 136.799,-31.303 ; -30.892,-26.138 -30.892,-41.632 70.835,-41.632 136.799,-41.632 136.799,-26.138 -30.88,-26.138 -30.88,-41.632 9.138,-41.632 ; 31.719,-41.632 31.719,-26.138 ; 63.901,-31.303 63.901,-26.138 ; 85.237,-31.303 85.237,-26.138 ; 101.035,-41.797 101.035,-36.645
  text "ALL ARTWORK VIEWED FROM TOP SIDE" at -29.279,-29.495 h1.52
  text "BOARD #:" at 33.624,-29.495 h1.52
  text ".PRJ_Number" at 47.479,-29.495 h1.52
  text "REV:" at 68.93,-29.495 h1.52
  text ".PCB_Rev" at 76.334,-29.495 h1.52
  text "SVN REV:" at 90.215,-29.495 h1.52
  text ".VersionControl_RevNumber" at 103.067,-29.495 h1.52
  text "LAYER NAME =" at -29.279,-34.647 h1.52
  text "TID #:" at 33.624,-34.66 h1.52
  text ".TID" at 47.479,-34.66 h1.52
  text "PLOT NAME =" at -29.279,-39.875 h1.52
  text ".plot_File_Name" at -8.82,-39.875 h1.52
  text "GENERATED    :" at 33.675,-39.875 h1.52
  text ".Print_Date" at 55.76,-39.875 h1.52
  text ".Print_Time" at 74.276,-39.875 h1.52
  text "TEXAS INSTRUMENTS" at 106.395,-39.875 h1.52
M12 Stackup:
  drawing of 292 lines, arcs and shapes, not listed
  text "STACKUP TABLE:" at 110.062,109.804 h2.03
  text "Layer" at 111.749,105.445 h1.52
  text "Name" at 122.161,105.445 h1.52
  text "Material" at 143.999,105.445 h1.52
  text "Thickness" at 165.837,105.445 h1.52
  text "Constant" at 182.343,105.445 h1.52
  text "Board Layer Stack" at 196.817,105.445 h1.52
  text "Board Layer Stack" at 225.257,105.445 h1.52
  text "1" at 111.749,102.397 h1.52
  text "Top Overlay" at 122.161,102.397 h1.52
  text "2" at 111.749,99.349 h1.52
  text "Top Solder" at 122.161,99.349 h1.52
  text "Solder Resist" at 143.999,99.349 h1.52
  text "0.40mil" at 165.837,99.349 h1.52
  text "3.5" at 182.343,99.349 h1.52
  text "3" at 111.749,96.301 h1.52
  text "Top Layer" at 122.161,96.301 h1.52
  text "Copper" at 143.999,96.301 h1.52
  text "2.10mil" at 165.837,96.301 h1.52
  text "4" at 111.749,93.253 h1.52
  text "Dielectric1" at 122.161,93.253 h1.52
  text "FR-4 High Tg" at 143.999,93.253 h1.52
  text "57.00mil" at 165.837,93.253 h1.52
  text "4.8" at 182.343,93.253 h1.52
  text "5" at 111.749,90.205 h1.52
  text "Bottom Layer" at 122.161,90.205 h1.52
  text "Copper" at 143.999,90.205 h1.52
  text "2.10mil" at 165.837,90.205 h1.52
  text "6" at 111.749,87.157 h1.52
  text "Bottom Solder" at 122.161,87.157 h1.52
  text "Solder Resist" at 143.999,87.157 h1.52
  text "0.40mil" at 165.837,87.157 h1.52
  text "3.5" at 182.343,87.157 h1.52
  text ".Layer_Name" at -8.82,-34.647 h1.52
M13 Component Bodies Top:
  text ".Layer_Name" at -8.82,-34.647 h1.52
M14 Component Bodies Bottom:
  text ".Layer_Name" at -8.82,-34.647 h1.52
M15 Courtyards Top:
  text ".Layer_Name" at -8.82,-34.647 h1.52
M16 Courtyards Bottom:
  text ".Layer_Name" at -8.82,-34.647 h1.52
Drill Drawing:
  circle w0.254: c112.586,71.626 r0.847
  lines w0.254: 111.739,52.153 112.163,52.153 112.586,51.73 113.009,52.153 113.433,52.153 113.009,52.576 113.433,53 113.009,53 112.586,53.423 112.163,53 111.739,53 112.163,52.576 111.739,52.153 ; 111.739,55.54 113.433,55.54 113.433,57.233 111.739,57.233 111.739,55.54 ; 111.739,66.97 112.586,67.393 113.433,66.97 113.009,67.816 113.433,68.663 112.586,68.24 111.739,68.663 112.163,67.816 111.739,66.97
  lines w0.381: 110.221,50.587 243.789,50.587 ; 110.221,77.257 243.789,77.257 ; 124.213,46.777 124.213,81.067 ; 139.195,46.777 139.195,81.067 ; 168.397,46.777 168.397,81.067 ; 181.246,46.777 181.246,81.067 ; 199.884,46.777 199.884,81.067 ; 227.969,46.777 227.969,81.067 ; 110.221,46.777 243.789,46.777 243.789,81.067 110.221,81.067 110.221,46.777
  text "Symbol" at 112.507,78.4 h1.83
  text "Count" at 125.356,78.4 h1.83
  text "Hole Size" at 140.338,78.4 h1.83
  text "Plated" at 169.54,78.4 h1.83
  text "Hole Type" at 182.389,78.4 h1.83
  text "Tolerance(Mils)" at 201.027,78.4 h1.83
  text "Tenting" at 229.112,78.4 h1.83
  text "DRILL TABLE:" at 110.24,75.828 h2.03
  text "109" at 125.356,74.59 h1.52
  text "12.00mil (0.305mm)" at 140.338,74.59 h1.52
  text "PTH" at 169.54,74.59 h1.52
  text "Round" at 182.389,74.59 h1.52
  text "+0/-12" at 201.027,74.59 h1.52
  text "Both" at 229.112,74.59 h1.52
  text "A" at 111.768,74.336 h1.69
  text "8" at 125.356,70.78 h1.52
  text "35.43mil (0.900mm)" at 140.338,70.78 h1.52
  text "PTH" at 169.54,70.78 h1.52
  text "Round" at 182.389,70.78 h1.52
  text "6" at 125.356,66.97 h1.52
  text "20.00mil (0.508mm)" at 140.338,66.97 h1.52
  text "PTH" at 169.54,66.97 h1.52
  text "Round" at 182.389,66.97 h1.52
  text "4" at 125.356,63.16 h1.52
  text "125.98mil (3.200mm)" at 140.338,63.16 h1.52
  text "PTH" at 169.54,63.16 h1.52
  text "Round" at 182.389,63.16 h1.52
  text "+/-3" at 201.027,63.16 h1.52
  text "D" at 111.768,62.906 h1.69
  text "3" at 125.356,59.35 h1.52
  text "214.57mil (5.450mm)" at 140.338,59.35 h1.52
  text "PTH" at 169.54,59.35 h1.52
  text "Round" at 182.389,59.35 h1.52
  text "+/-3" at 201.027,59.35 h1.52
  text "E" at 111.768,59.096 h1.69
  text "2" at 125.356,55.54 h1.52
  text "40.00mil (1.016mm)" at 140.338,55.54 h1.52
  text "PTH" at 169.54,55.54 h1.52
  text "Round" at 182.389,55.54 h1.52
  text "2" at 125.356,51.73 h1.52
  text "51.18mil (1.300mm)" at 140.338,51.73 h1.52
  text "PTH" at 169.54,51.73 h1.52
  text "Round" at 182.389,51.73 h1.52
  text "134 Total" at 125.356,47.92 h1.52
  text ".Layer_Name" at -8.82,-34.647 h1.52
M17 Embedded Cavity:
  text ".Layer_Name" at -8.82,-34.647 h1.52
M18 Embedded Assembly:
  text ".Layer_Name" at -8.82,-34.647 h1.52
M19 Embedded Keepout:
  text ".Layer_Name" at -8.82,-34.647 h1.52

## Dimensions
4.445,4.445 to 0,0 on M2 Board Dimensions
4.445,4.445 to 0,0 on M2 Board Dimensions
4.445,4.445 to 0,53.34 on M2 Board Dimensions
4.445,4.445 to 79.375,0 on M2 Board Dimensions
-23.475,-23.001 to 1.925,-23.001 on M2 Board Dimensions
3.724,3.678 to -3.504,-1.911 on M2 Board Dimensions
